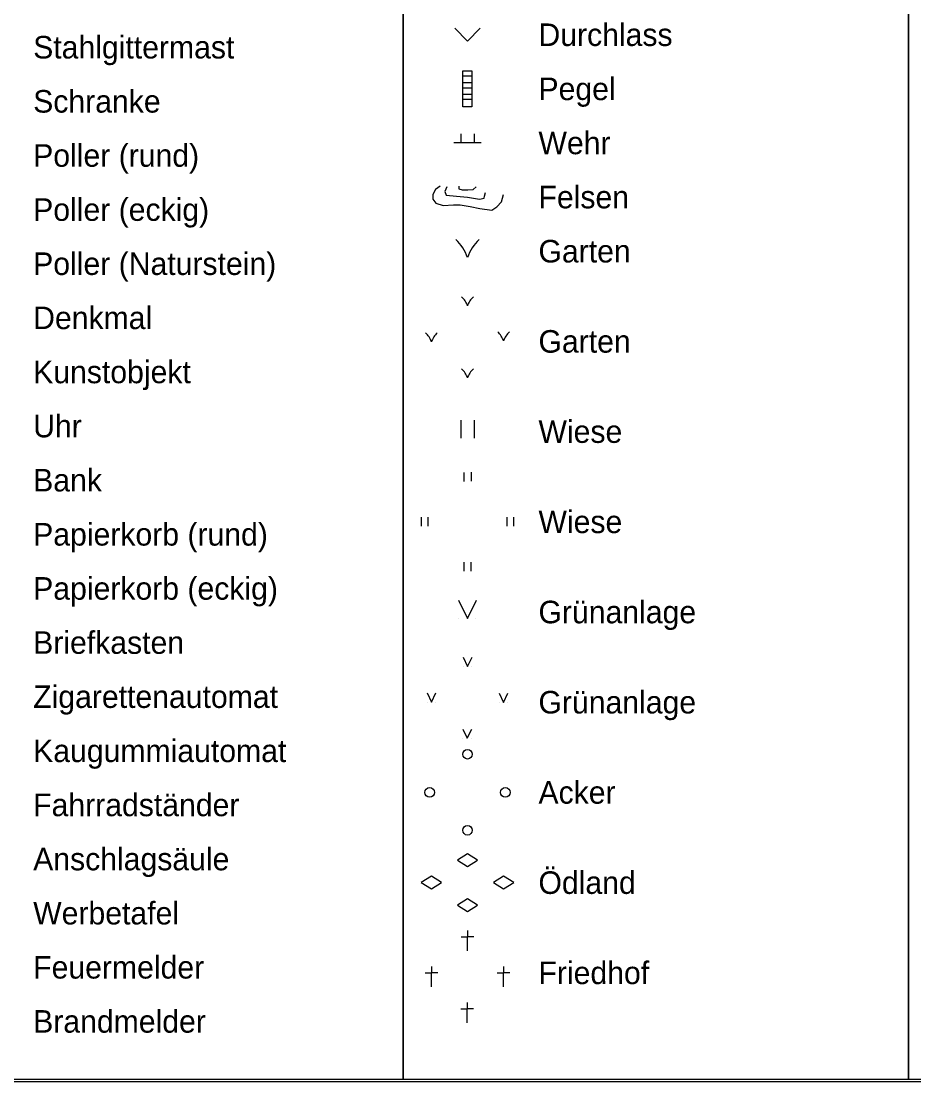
# Model space of a CAD drawing. Extents: x 679244 to 679420, y 5639809 to 5639932.
# Drawn here: x 679283.1 to 679332.6, y 5639808.5 to 5639867.3 of the extents above; entities that cross this region are included whole.
import ezdxf

# ---------------------------------------------------------------- set-up
doc = ezdxf.new("R2010")
doc.units = 0
for name, color, linetype in [('Acker', 7, 'Continuous'), ('Default', 7, 'Continuous'), ('Durchlass', 7, 'Continuous'), ('Felsen', 7, 'Continuous'), ('Friedhof', 7, 'Continuous'), ('Garten', 7, 'Continuous'), ('Gruenanlage', 7, 'Continuous'), ('Oedland', 7, 'Continuous'), ('Pegel', 7, 'Continuous'), ('Rahmen_1', 7, 'Continuous'), ('Wehr', 7, 'Continuous'), ('Wiese', 7, 'Continuous')]:
    doc.layers.add(name, color=color, linetype=linetype)

msp = doc.modelspace()

# ---------------------------------------------------------------- linework, layer by layer
at = {"layer": 'Acker'}
for centre in [(679307.844, 5639826.672), (679305.748, 5639824.555), (679309.942, 5639824.556), (679307.844, 5639822.458)]:
    msp.add_circle(centre, 0.266, dxfattribs=at)
at = {"layer": 'Default'}
for points in [[(679276.286, 5639808.666), (679304.286, 5639808.666), (679304.286, 5639928.666), (679276.286, 5639928.666)], [(679304.286, 5639808.666), (679332.286, 5639808.666), (679332.286, 5639928.666), (679304.286, 5639928.666)], [(679332.286, 5639808.666), (679360.286, 5639808.666), (679360.286, 5639928.666), (679332.286, 5639928.666)]]:
    msp.add_lwpolyline(points, close=True, dxfattribs=at)
at = {"layer": 'Durchlass'}
msp.add_lwpolyline([(679307.137, 5639866.909), (679307.844, 5639866.201), (679308.551, 5639866.909)], dxfattribs=at)
at = {"layer": 'Felsen'}
for points in [[(679306.327, 5639858.156), (679306.069, 5639857.984), (679305.926, 5639857.698), (679305.926, 5639857.44), (679306.098, 5639857.211), (679306.499, 5639857.096), (679307.071, 5639857.125), (679307.443, 5639857.125), (679307.987, 5639857.039), (679308.531, 5639856.924), (679309.19, 5639856.838), (679309.476, 5639857.01), (679309.734, 5639857.297), (679309.848, 5639857.698)], [(679306.699, 5639858.128), (679306.584, 5639857.87), (679306.67, 5639857.669), (679307.243, 5639857.612), (679307.844, 5639857.555), (679308.503, 5639857.44), (679308.76, 5639857.497), (679308.789, 5639857.612), (679308.846, 5639857.812)], [(679307.357, 5639858.156), (679307.357, 5639858.013), (679307.558, 5639857.956), (679307.873, 5639857.956), (679308.159, 5639857.984), (679308.331, 5639858.128)]]:
    msp.add_lwpolyline(points, dxfattribs=at)
at = {"layer": 'Friedhof'}
for p, q in [((679307.851, 5639816.902), (679307.851, 5639816.552)), ((679307.501, 5639816.552), (679307.851, 5639816.552)), ((679308.201, 5639816.552), (679307.851, 5639816.552)), ((679307.851, 5639815.777), (679307.851, 5639816.552)), ((679305.495, 5639814.548), (679305.845, 5639814.548)), ((679305.845, 5639814.898), (679305.845, 5639814.548)), ((679306.195, 5639814.548), (679305.845, 5639814.548)), ((679305.845, 5639813.773), (679305.845, 5639814.548)), ((679309.492, 5639814.561), (679309.842, 5639814.561)), ((679309.842, 5639814.911), (679309.842, 5639814.561)), ((679310.192, 5639814.561), (679309.842, 5639814.561)), ((679309.842, 5639813.786), (679309.842, 5639814.561)), ((679307.834, 5639812.902), (679307.834, 5639812.552)), ((679307.484, 5639812.552), (679307.834, 5639812.552)), ((679308.184, 5639812.552), (679307.834, 5639812.552)), ((679307.834, 5639811.777), (679307.834, 5639812.552))]:
    msp.add_line(p, q, dxfattribs=at)
at = {"layer": 'Garten'}
for centre, radius, start, end in [((679305.691, 5639853.512), 2.26, 17.72666, 48.32108), ((679309.997, 5639853.512), 2.26, 131.67892, 162.27334), ((679306.768, 5639851.181), 1.13, 17.72666, 48.32108), ((679308.921, 5639851.181), 1.13, 131.67892, 162.27334), ((679304.769, 5639849.185), 1.13, 17.72666, 48.32108), ((679306.922, 5639849.185), 1.13, 131.67892, 162.27334), ((679308.77, 5639849.236), 1.13, 17.72666, 48.32108), ((679310.923, 5639849.236), 1.13, 131.67892, 162.27334), ((679306.768, 5639847.186), 1.13, 17.72666, 48.32108), ((679308.921, 5639847.186), 1.13, 131.67892, 162.27334)]:
    msp.add_arc(centre, radius, start, end, dxfattribs=at)
at = {"layer": 'Gruenanlage'}
for p, q in [((679307.353, 5639834.168), (679307.353, 5639834.168)), ((679308.303, 5639834.201), (679308.303, 5639834.201)), ((679307.607, 5639831.52), (679307.607, 5639831.52)), ((679308.082, 5639831.536), (679308.082, 5639831.536)), ((679305.602, 5639829.546), (679305.602, 5639829.546)), ((679306.077, 5639829.562), (679306.077, 5639829.562)), ((679309.596, 5639829.53), (679309.596, 5639829.53)), ((679310.071, 5639829.547), (679310.071, 5639829.547)), ((679307.591, 5639827.541), (679307.591, 5639827.541)), ((679308.066, 5639827.557), (679308.066, 5639827.557))]:
    msp.add_line(p, q, dxfattribs=at)
for points in [[(679307.353, 5639835.217), (679307.844, 5639834.201), (679308.336, 5639835.217)], [(679307.607, 5639832.044), (679307.852, 5639831.536), (679308.098, 5639832.044)], [(679305.602, 5639830.07), (679305.848, 5639829.562), (679306.094, 5639830.07)], [(679309.596, 5639830.055), (679309.841, 5639829.547), (679310.087, 5639830.055)], [(679307.591, 5639828.065), (679307.836, 5639827.557), (679308.082, 5639828.065)]]:
    msp.add_lwpolyline(points, dxfattribs=at)
at = {"layer": 'Oedland'}
for points in [[(679308.407, 5639820.799), (679307.844, 5639821.149), (679307.282, 5639820.799), (679307.844, 5639820.449)], [(679306.407, 5639819.555), (679305.844, 5639819.905), (679305.282, 5639819.555), (679305.844, 5639819.205)], [(679310.407, 5639819.555), (679309.844, 5639819.905), (679309.282, 5639819.555), (679309.844, 5639819.205)], [(679308.407, 5639818.31), (679307.844, 5639818.66), (679307.282, 5639818.31), (679307.844, 5639817.96)]]:
    msp.add_lwpolyline(points, close=True, dxfattribs=at)
at = {"layer": 'Pegel'}
for points in [[(679307.594, 5639864.555), (679308.094, 5639864.555), (679308.094, 5639862.555), (679307.594, 5639862.555)], [(679307.594, 5639864.555), (679308.094, 5639864.555), (679308.094, 5639864.255), (679307.594, 5639864.255)], [(679307.594, 5639863.897), (679308.094, 5639863.897), (679308.094, 5639863.597), (679307.594, 5639863.597)], [(679307.594, 5639863.256), (679308.094, 5639863.256), (679308.094, 5639862.956), (679307.594, 5639862.956)]]:
    msp.add_lwpolyline(points, close=True, dxfattribs=at)
at = {"layer": 'Rahmen_1'}
msp.add_lwpolyline([(679419.991, 5639808.515), (679243.507, 5639808.515), (679243.507, 5639931.667), (679419.991, 5639931.667)], close=True, dxfattribs=at)
at = {"layer": 'Wehr'}
for p, q in [((679307.47, 5639861.055), (679307.47, 5639860.555)), ((679308.22, 5639861.055), (679308.22, 5639860.555)), ((679308.594, 5639860.555), (679307.095, 5639860.555))]:
    msp.add_line(p, q, dxfattribs=at)
at = {"layer": 'Wiese'}
for p, q in [((679307.469, 5639845.194), (679307.469, 5639844.194)), ((679308.219, 5639845.194), (679308.219, 5639844.194)), ((679307.649, 5639842.294), (679307.649, 5639841.794)), ((679308.04, 5639842.302), (679308.04, 5639841.802)), ((679305.275, 5639839.805), (679305.275, 5639839.305)), ((679305.65, 5639839.805), (679305.65, 5639839.305)), ((679310.025, 5639839.805), (679310.025, 5639839.305)), ((679310.4, 5639839.805), (679310.4, 5639839.305)), ((679307.64, 5639837.311), (679307.64, 5639836.811)), ((679308.023, 5639837.317), (679308.023, 5639836.817))]:
    msp.add_line(p, q, dxfattribs=at)

# ---------------------------------------------------------------- texts
at = {"layer": 'Default'}
for s, p in [('Durchlass', (679311.778, 5639865.93)), ('Stahlgittermast', (679283.778, 5639865.237)), ('Pegel', (679311.778, 5639862.93)), ('Schranke', (679283.778, 5639862.237)), ('Wehr', (679311.778, 5639859.93)), ('Poller (rund)', (679283.778, 5639859.237)), ('Felsen', (679311.778, 5639856.93)), ('Poller (eckig)', (679283.778, 5639856.237)), ('Garten ', (679311.778, 5639853.93)), ('Poller (Naturstein)', (679283.778, 5639853.237)), ('Denkmal', (679283.778, 5639850.237)), ('Garten', (679311.778, 5639848.93)), ('Kunstobjekt', (679283.778, 5639847.237)), ('Uhr', (679283.778, 5639844.237)), ('Wiese ', (679311.778, 5639843.93)), ('Bank', (679283.778, 5639841.237)), ('Wiese', (679311.778, 5639838.93)), ('Papierkorb (rund)', (679283.778, 5639838.237)), ('Papierkorb (eckig)', (679283.778, 5639835.237)), ('Grünanlage ', (679311.778, 5639833.93)), ('Briefkasten', (679283.778, 5639832.237)), ('Zigarettenautomat', (679283.778, 5639829.237)), ('Grünanlage ', (679311.778, 5639828.93)), ('Kaugummiautomat', (679283.778, 5639826.237)), ('Acker', (679311.778, 5639823.93)), ('Fahrradständer', (679283.778, 5639823.237)), ('Anschlagsäule', (679283.778, 5639820.237)), ('Ödland', (679311.778, 5639818.93)), ('Werbetafel', (679283.778, 5639817.237)), ('Feuermelder', (679283.778, 5639814.237)), ('Friedhof', (679311.778, 5639813.93)), ('Brandmelder', (679283.778, 5639811.237))]:
    msp.add_text(s, height=1.25, dxfattribs=at).set_placement(p)

doc.saveas('drawing.dxf')
